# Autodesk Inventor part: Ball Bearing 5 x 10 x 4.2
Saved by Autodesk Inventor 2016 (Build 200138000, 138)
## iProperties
Created: 2015-11
Part Number: Ball Bearing 5 x 10 x 4.2
Material: Generic
Document SubType Name: Modeling
Designer: John
Density: 1 g/cm^3
Appearance: Default
Author: John
Revision Number: ANY
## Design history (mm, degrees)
feature "Revolve1"
body "Solid1"
